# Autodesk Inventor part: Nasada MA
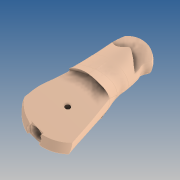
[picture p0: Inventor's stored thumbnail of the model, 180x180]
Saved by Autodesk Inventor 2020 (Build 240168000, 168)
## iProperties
Created: 2019-10
Part Number: Nasada MA
Material: GFRP
Document SubType Name: Modeling
Designer: yello
Density: 1.75 g/cm^3
Appearance: Default
Author: yello
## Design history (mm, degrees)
feature "Nasada MA"
workplane "Work Plane1"
sketch "Sketch2"
  geometry: L1 (-3.5, 0)-(-3.5, -20); L2 (-3.5, -20)-(3.5, -20); L3 (3.5, -20)-(3.5, 0); L4 (3.5, 0)-(3.5, 30); L5 (3.5, 30)-(-3.5, 30); L6 (-3.5, 30)-(-3.5, 0); L7 (0, 30)-(0, -20); L8 (0, 8.502)-(0, 11.113) reference; A1 r 3.5 centre (0, 0) between (-3.5, 0) and (3.5, 0)
  constraints: 16 end point, 3 perpendicular, 2 midpoint, 2 point on circle, 2 point on line, 2 tangent, 1 centre point, 1 collinear, 1 vertical, 2 other
  dimensions: "d1" = 7 diameter of A1; "d2" = 20 distance of L1.start L1.end; "d3" = 30 distance of L3.end L4.end
revolve "Revolution1" sketch "Sketch2" stored, may be unused: angle "d4" = 90 deg
workplane "Work Plane2"
sketch "Sketch3"
  geometry: C1 r 4.25 at (0, 0)
  constraints: 1 centre point
  dimensions: "d6" = 8.5 diameter of C1
extrude "Extrusion1" cut sketch "Sketch3" distance "d7" = 1.75; taper "d8" = 0 deg
workplane "Work Plane3"
sketch "Sketch4" dims "d11" = 3
  geometry: L1 (-3.403, 29.08)-(-11.266, 0.129); L2 (-11.266, 0.129)-(-11.66, -1.318); L3 (-0.025, 28.163)-(-6.78, 29.998) reference; 2 further points
  constraints: 4 end point, 1 coincident, 3 other
  dimensions: "d22" = 30 distance from line of L3 L2.start
revolve "Revolution2" sketch "Sketch4" stored, may be unused: angle "d12" = 90 deg
mirror "Mirror2"
workplane "Work Plane4"
sketch "Sketch7"
  geometry: L1 (-10, 3.5)-(-6.25, 3.5); L2 (-6.25, 3.5)-(2, 3.5); L3 (-6.25, 2.5)-(2, 2.5); L4 (2, 4.5)-(-6.25, 4.5); L5 (-10, 7)-(-10, 0) reference; A1 r 1 centre (-6.25, 3.5) between (-6.25, 4.5) and (-6.25, 2.5); A2 r 1 centre (2, 3.5) between (2, 2.5) and (2, 4.5); 1 further point
  constraints: 10 end point, 4 point on circle, 4 tangent, 2 centre point, 2 horizontal, 1 midpoint, 1 parallel
  dimensions: "d16" = 3.75 distance of L1.start L1.end; "d17" = 8.25 distance of L1.end L2.end; "d18" = 2 diameter of A2; "d23" = 0 distance from line of L5 L1.start
extrude "Extrusion3" cut sketch "Sketch7" distance "d19" = 3453; taper "d20" = 0 deg
fillet "Fillet1" dims "d21" = 1
body "Solid1"
other parameters: "d5" = 38, "d9" = -0.5
